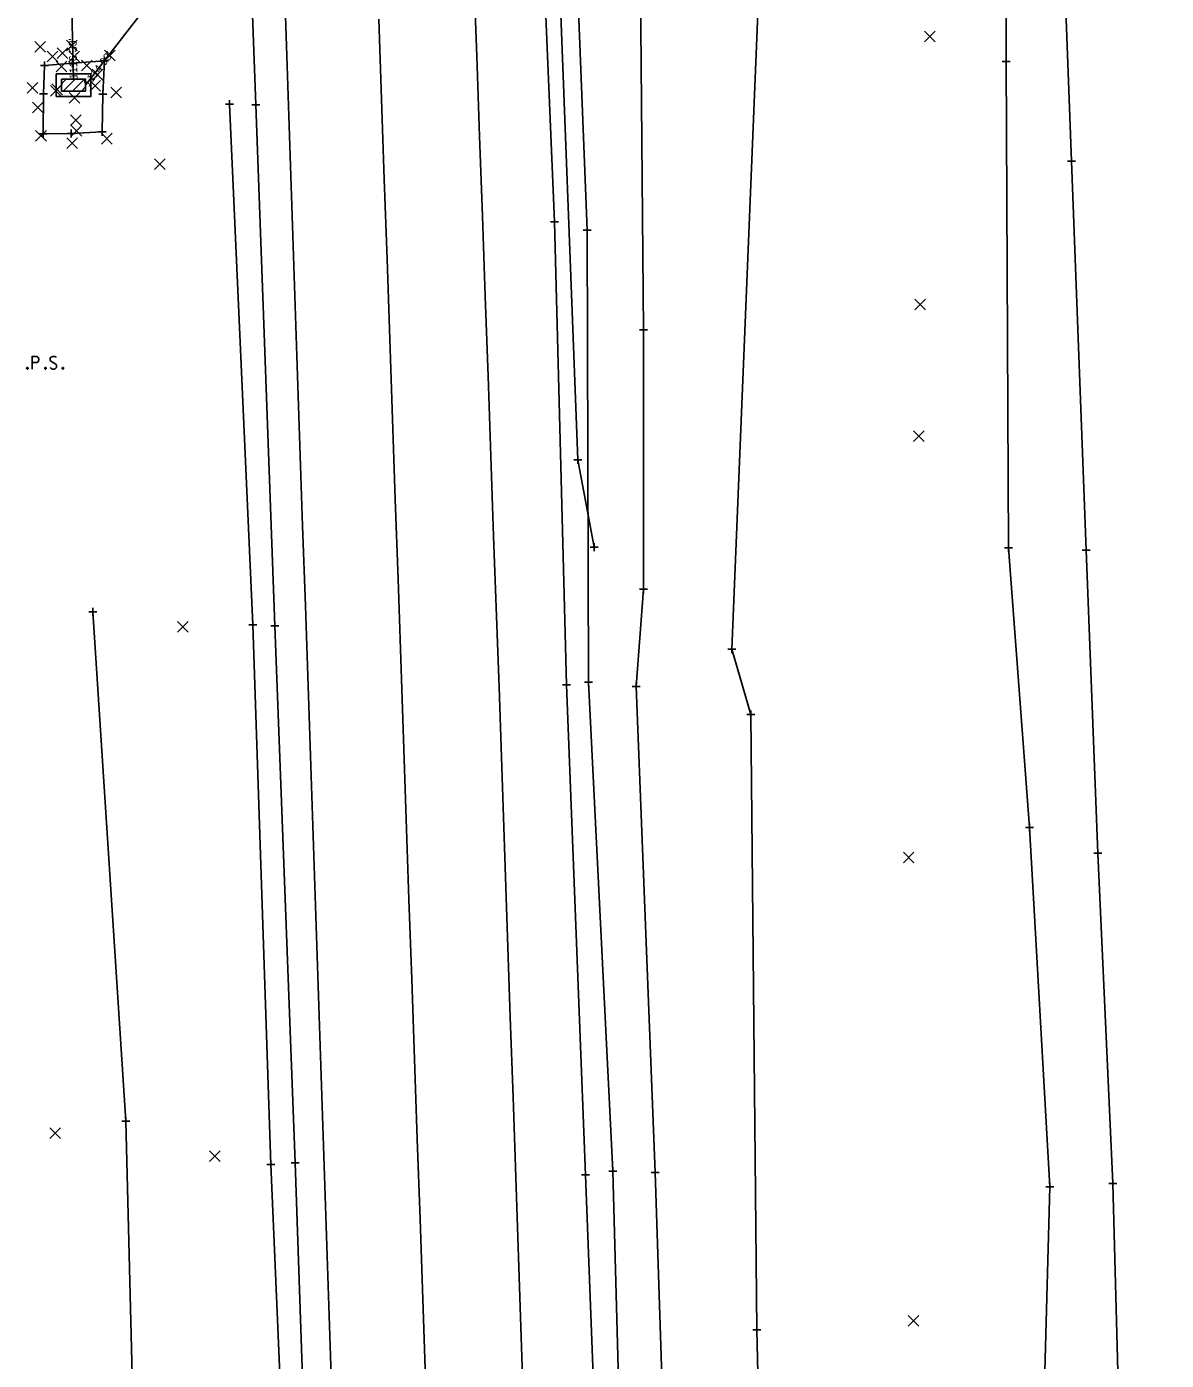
# Model space of a CAD drawing. Extents: x 146022 to 147632, y 437624 to 440659.
# Drawn here: x 146985.9 to 147128.3, y 438299.4 to 438466 of the extents above; entities that cross this region are included whole.
import ezdxf

# ---------------------------------------------------------------- set-up
doc = ezdxf.new("R2010")
doc.units = 0
for name, color, linetype in [('_CIVIL_CONSTRUCTION', 7, 'Continuous'), ('BR_P_Rail_Object', 7, 'Continuous'), ('DR_P_Ditch', 7, 'Continuous'), ('DR_P_Paved_Gutter', 7, 'Continuous'), ('DR_X_Storm_Sewer', 7, 'Continuous'), ('DT_X_Triangles', 7, 'Continuous'), ('PF_X_Ground_Line', 7, 'Continuous'), ('PV_P_Curb', 7, 'Continuous'), ('PV_P_Shoulder', 7, 'Continuous'), ('RD_P_Anchor_Assembly', 7, 'Continuous'), ('RD_P_Fence', 7, 'Continuous'), ('RD_P_GR_Lt_Replaced', 7, 'Continuous'), ('SC_Scratch1', 7, 'Continuous'), ('SC_Scratch3', 7, 'Continuous'), ('SV_X_Terrain_Boundary', 7, 'Continuous'), ('UT_X_Electric', 7, 'Continuous')]:
    doc.layers.add(name, color=color, linetype=linetype)

msp = doc.modelspace()

# ---------------------------------------------------------------- linework, layer by layer
at = {"layer": '_CIVIL_CONSTRUCTION'}
for p, q in [((147098.11, 438464.09), (147099.45, 438465.43)), ((147098.11, 438465.43), (147099.45, 438464.09)), ((146986.96, 438462.83), (146988.3, 438464.16)), ((146986.96, 438464.16), (146988.3, 438462.83)), ((146988.51, 438461.61), (146989.84, 438462.95)), ((146988.51, 438462.95), (146989.84, 438461.61)), ((146989.73, 438462.03), (146991.06, 438463.37)), ((146989.73, 438463.37), (146991.06, 438462.03)), ((146990.9, 438462.99), (146992.23, 438464.32)), ((146990.9, 438464.32), (146992.23, 438462.99)), ((146991.22, 438461.6), (146992.55, 438462.93)), ((146991.22, 438462.93), (146992.55, 438461.6)), ((146995.67, 438461.73), (146997, 438463.06)), ((146995.67, 438463.06), (146997, 438461.73)), ((146989.62, 438460.35), (146990.95, 438461.68)), ((146989.62, 438461.68), (146990.95, 438460.35)), ((146992.77, 438460.48), (146994.1, 438461.82)), ((146992.77, 438461.82), (146994.1, 438460.48)), ((146994.12, 438459.33), (146995.45, 438460.67)), ((146994.12, 438460.67), (146995.45, 438459.33)), ((146985.98, 438457.67), (146987.32, 438459)), ((146985.98, 438459), (146987.32, 438457.67)), ((146988.9, 438457.32), (146990.23, 438458.66)), ((146988.9, 438458.66), (146990.23, 438457.32)), ((146989.09, 438457.5), (146990.42, 438458.84)), ((146989.09, 438458.84), (146990.42, 438457.5)), ((146991.26, 438456.44), (146992.59, 438457.77)), ((146991.26, 438457.77), (146992.59, 438456.44)), ((146993.81, 438457.93), (146995.14, 438459.26)), ((146993.81, 438459.26), (146995.14, 438457.93)), ((146996.44, 438457.11), (146997.78, 438458.44)), ((146996.44, 438458.44), (146997.78, 438457.11)), ((146986.68, 438455.23), (146988.01, 438456.56)), ((146986.68, 438456.56), (146988.01, 438455.23)), ((146991.4, 438453.66), (146992.73, 438454.99)), ((146991.4, 438454.99), (146992.73, 438453.66)), ((146987.05, 438451.69), (146988.39, 438453.03)), ((146987.05, 438453.03), (146988.39, 438451.69)), ((146991.49, 438452.32), (146992.83, 438453.65)), ((146991.49, 438453.65), (146992.83, 438452.32)), ((146990.96, 438450.77), (146992.3, 438452.11)), ((146990.96, 438452.11), (146992.3, 438450.77)), ((146995.28, 438451.33), (146996.61, 438452.67)), ((146995.28, 438452.67), (146996.61, 438451.33)), ((147001.91, 438448.14), (147003.24, 438449.47)), ((147001.91, 438449.47), (147003.24, 438448.14)), ((147096.9, 438430.62), (147098.23, 438431.95)), ((147096.9, 438431.95), (147098.23, 438430.62)), ((147096.74, 438414.17), (147098.07, 438415.51)), ((147096.74, 438415.51), (147098.07, 438414.17)), ((147004.79, 438390.35), (147006.12, 438391.68)), ((147004.79, 438391.68), (147006.12, 438390.35)), ((147095.47, 438361.51), (147096.8, 438362.84)), ((147095.47, 438362.84), (147096.8, 438361.51)), ((146988.83, 438327.07), (146990.16, 438328.41)), ((146988.83, 438328.41), (146990.16, 438327.07)), ((147008.79, 438324.21), (147010.12, 438325.54)), ((147008.79, 438325.54), (147010.12, 438324.21)), ((147096.07, 438303.63), (147097.41, 438304.97)), ((147096.07, 438304.97), (147097.41, 438303.63))]:
    msp.add_line(p, q, dxfattribs=at)
at = {"layer": 'BR_P_Rail_Object'}
for points in [[(147119.79, 438362.73), (147118.32, 438400.57), (147116.48, 438449.21), (147113.81, 438520.22)], [(147128.33, 438146.75), (147127.41, 438176.4), (147123.32, 438258.89), (147121.66, 438321.45), (147119.79, 438362.73)]]:
    msp.add_lwpolyline(points, dxfattribs=at)
at = {"layer": 'DR_P_Ditch'}
msp.add_lwpolyline([(146988, 438452.59), (146988.04, 438457.62), (146988.17, 438461.16), (146991.65, 438461.43), (146995.67, 438461.74), (146995.45, 438457.58), (146995.38, 438452.85), (146991.51, 438452.66)], close=True, dxfattribs=at)
at = {"layer": 'DR_P_Paved_Gutter'}
msp.add_lwpolyline([(147056.84, 438400.98), (147054.81, 438411.86), (147052.17, 438480.63), (147047.3, 438600.68)], dxfattribs=at)
at = {"layer": 'DR_X_Storm_Sewer'}
for p, q in [((146991.79, 438459.44), (146989.6, 438545.12)), ((146993.29, 438458.69), (147010.8, 438481.43))]:
    msp.add_line(p, q, dxfattribs=at)
at = {"layer": 'DT_X_Triangles'}
for p, q in [((146991.79, 438460.11), (146991.79, 438460.11)), ((146991.79, 438459.44), (146991.79, 438459.44)), ((146991.79, 438459.44), (146991.79, 438459.44)), ((146991.79, 438459.44), (146991.79, 438459.44)), ((146990.29, 438458.69), (146990.29, 438458.69)), ((146991.79, 438458.69), (146991.79, 438458.69)), ((146991.79, 438457.94), (146991.79, 438457.94)), ((146993.29, 438458.69), (146993.29, 438458.69)), ((146991.79, 438457.28), (146991.79, 438457.28))]:
    msp.add_line(p, q, dxfattribs=at)
at = {"layer": 'PF_X_Ground_Line'}
for p, q in [((147074.02, 438388.21), (147077.83, 438481.37)), ((147108.63, 438400.88), (147111.24, 438365.93)), ((147074.02, 438388.21), (147076.41, 438380.04))]:
    msp.add_line(p, q, dxfattribs=at)
for points in [[(147108.63, 438400.88), (147108.31, 438461.63), (147108.54, 438516.2)], [(147064.97, 438144.61), (147062.9, 438206.3), (147060.74, 438264.49), (147059.17, 438322.98), (147056.14, 438384.08), (147055.96, 438440.58), (147053.73, 438497.65)], [(147022.87, 438144.98), (147021.12, 438202.84), (147018.92, 438265.58), (147016.42, 438323.84), (147014.17, 438391.24), (147011.28, 438456.3)], [(147076.41, 438380.04), (147077.15, 438303.18), (147078.67, 438238.93), (147079.52, 438175.99), (147079.42, 438144.26)], [(147118.6, 438141.07), (147114.52, 438172.8), (147112.25, 438264.18), (147113.76, 438321.03), (147111.24, 438365.93)]]:
    msp.add_lwpolyline(points, dxfattribs=at)
at = {"layer": 'PV_P_Curb'}
msp.add_lwpolyline([(147035.76, 438297.02), (147035.42, 438307.01), (147035.08, 438317.01), (147034.73, 438327), (147034.39, 438337), (147034.05, 438346.99), (147033.7, 438356.98), (147033.36, 438366.98), (147033.02, 438376.97), (147032.67, 438386.97), (147032.33, 438396.96), (147031.99, 438406.95), (147031.64, 438416.95), (147031.3, 438426.94), (147030.96, 438436.94), (147030.61, 438446.93), (147030.27, 438456.93), (147029.93, 438466.92)], dxfattribs=at)
at = {"layer": 'PV_P_Shoulder'}
for points in [[(146986.6, 438423.2), (146986.6, 438424.8), (146987.13, 438424.8), (146987.19, 438424.79), (146987.27, 438424.76), (146987.3, 438424.74), (146987.33, 438424.71), (146987.38, 438424.65), (146987.41, 438424.59), (146987.43, 438424.49), (146987.43, 438424.34), (146987.42, 438424.29), (146987.4, 438424.21), (146987.35, 438424.12), (146987.31, 438424.08), (146987.28, 438424.06), (146987.22, 438424.03), (146987.13, 438424.02), (146986.6, 438424.02)], [(146989.61, 438424.69), (146989.59, 438424.71), (146989.56, 438424.74), (146989.46, 438424.78), (146989.34, 438424.8), (146989.25, 438424.8), (146989.22, 438424.8), (146989.07, 438424.76), (146988.95, 438424.69), (146988.87, 438424.59), (146988.85, 438424.49), (146988.85, 438424.41), (146988.87, 438424.31), (146988.96, 438424.22), (146989.57, 438423.84), (146989.62, 438423.79), (146989.65, 438423.74), (146989.67, 438423.67), (146989.67, 438423.59), (146989.66, 438423.52), (146989.65, 438423.47), (146989.62, 438423.4), (146989.6, 438423.35), (146989.58, 438423.32), (146989.55, 438423.28), (146989.51, 438423.25), (146989.47, 438423.23), (146989.44, 438423.21), (146989.34, 438423.2), (146989.18, 438423.2), (146989.08, 438423.23), (146988.94, 438423.32), (146988.85, 438423.39)], [(146986, 438423.42), (146986.05, 438423.42), (146986.09, 438423.39), (146986.12, 438423.34), (146986.12, 438423.28), (146986.09, 438423.23), (146986.05, 438423.2), (146986, 438423.2), (146985.96, 438423.23), (146985.93, 438423.28), (146985.93, 438423.34), (146985.96, 438423.39), (146986, 438423.42)], [(146988.25, 438423.42), (146988.3, 438423.42), (146988.33, 438423.39), (146988.37, 438423.34), (146988.37, 438423.28), (146988.33, 438423.23), (146988.3, 438423.2), (146988.25, 438423.2), (146988.21, 438423.23), (146988.18, 438423.28), (146988.18, 438423.34), (146988.21, 438423.39), (146988.25, 438423.42)], [(146990.43, 438423.42), (146990.48, 438423.42), (146990.52, 438423.39), (146990.55, 438423.34), (146990.55, 438423.28), (146990.52, 438423.23), (146990.48, 438423.2), (146990.43, 438423.2), (146990.4, 438423.23), (146990.36, 438423.28), (146990.36, 438423.34), (146990.4, 438423.39), (146990.43, 438423.42)]]:
    msp.add_lwpolyline(points, dxfattribs=at)
at = {"layer": 'RD_P_Anchor_Assembly'}
for p, q in [((146987.67, 438461.16), (146988.67, 438461.16)), ((146988.17, 438461.66), (146988.17, 438460.66)), ((146988.17, 438461.16), (146988.17, 438461.16)), ((146991.15, 438461.43), (146992.15, 438461.43)), ((146991.65, 438461.93), (146991.65, 438460.93)), ((146991.65, 438461.43), (146991.65, 438461.43)), ((146995.17, 438461.74), (146996.17, 438461.74)), ((146995.67, 438462.24), (146995.67, 438461.24)), ((146995.67, 438461.74), (146995.67, 438461.74)), ((147107.81, 438461.63), (147108.81, 438461.63)), ((147108.31, 438462.13), (147108.31, 438461.13)), ((147108.31, 438461.63), (147108.31, 438461.63)), ((146988.04, 438458.12), (146988.04, 438457.12)), ((146995.45, 438458.08), (146995.45, 438457.08)), ((146987.54, 438457.62), (146988.54, 438457.62)), ((146988.04, 438457.62), (146988.04, 438457.62)), ((146994.95, 438457.58), (146995.95, 438457.58)), ((146995.45, 438457.58), (146995.45, 438457.58)), ((147010.78, 438456.3), (147011.78, 438456.3)), ((147011.28, 438456.8), (147011.28, 438455.8)), ((147011.28, 438456.3), (147011.28, 438456.3)), ((147014.05, 438456.21), (147015.05, 438456.21)), ((147014.55, 438456.71), (147014.55, 438455.71)), ((147014.55, 438456.21), (147014.55, 438456.21)), ((146988, 438453.09), (146988, 438452.09)), ((146991.51, 438453.16), (146991.51, 438452.16)), ((146994.88, 438452.85), (146995.88, 438452.85)), ((146995.38, 438453.35), (146995.38, 438452.35)), ((146995.38, 438452.85), (146995.38, 438452.85)), ((146987.5, 438452.59), (146988.5, 438452.59)), ((146988, 438452.59), (146988, 438452.59)), ((146991.01, 438452.66), (146992.01, 438452.66)), ((146991.51, 438452.66), (146991.51, 438452.66)), ((147116.48, 438449.71), (147116.48, 438448.71)), ((147115.98, 438449.21), (147116.98, 438449.21)), ((147116.48, 438449.21), (147116.48, 438449.21)), ((147051.4, 438441.59), (147052.4, 438441.59)), ((147051.9, 438442.09), (147051.9, 438441.09)), ((147051.9, 438441.59), (147051.9, 438441.59)), ((147055.96, 438441.08), (147055.96, 438440.08)), ((147055.46, 438440.58), (147056.46, 438440.58)), ((147055.96, 438440.58), (147055.96, 438440.58)), ((147062.49, 438428.1), (147063.49, 438428.1)), ((147062.99, 438428.6), (147062.99, 438427.6)), ((147062.99, 438428.1), (147062.99, 438428.1)), ((147054.31, 438411.86), (147055.31, 438411.86)), ((147054.81, 438412.36), (147054.81, 438411.36)), ((147054.81, 438411.86), (147054.81, 438411.86)), ((147056.84, 438401.48), (147056.84, 438400.48)), ((147108.63, 438401.38), (147108.63, 438400.38)), ((147056.34, 438400.98), (147057.34, 438400.98)), ((147056.84, 438400.98), (147056.84, 438400.98)), ((147108.13, 438400.88), (147109.13, 438400.88)), ((147108.63, 438400.88), (147108.63, 438400.88)), ((147117.82, 438400.57), (147118.82, 438400.57)), ((147118.32, 438401.07), (147118.32, 438400.07)), ((147118.32, 438400.57), (147118.32, 438400.57)), ((147063.01, 438396.22), (147063.01, 438395.22)), ((147062.51, 438395.72), (147063.51, 438395.72)), ((147063.01, 438395.72), (147063.01, 438395.72)), ((146993.7, 438392.86), (146994.7, 438392.86)), ((146994.2, 438393.36), (146994.2, 438392.36)), ((146994.2, 438392.86), (146994.2, 438392.86)), ((147013.67, 438391.24), (147014.67, 438391.24)), ((147014.17, 438391.74), (147014.17, 438390.74)), ((147014.17, 438391.24), (147014.17, 438391.24)), ((147016.44, 438391.13), (147017.44, 438391.13)), ((147016.94, 438391.63), (147016.94, 438390.63)), ((147016.94, 438391.13), (147016.94, 438391.13)), ((147073.52, 438388.21), (147074.52, 438388.21)), ((147074.02, 438388.71), (147074.02, 438387.71)), ((147074.02, 438388.21), (147074.02, 438388.21)), ((147056.14, 438384.58), (147056.14, 438383.58)), ((147052.89, 438383.76), (147053.89, 438383.76)), ((147053.39, 438384.26), (147053.39, 438383.26)), ((147053.39, 438383.76), (147053.39, 438383.76)), ((147055.64, 438384.08), (147056.64, 438384.08)), ((147056.14, 438384.08), (147056.14, 438384.08)), ((147061.57, 438383.55), (147062.57, 438383.55)), ((147062.07, 438384.05), (147062.07, 438383.05)), ((147062.07, 438383.55), (147062.07, 438383.55)), ((147075.91, 438380.04), (147076.91, 438380.04)), ((147076.41, 438380.54), (147076.41, 438379.54)), ((147076.41, 438380.04), (147076.41, 438380.04)), ((147111.24, 438366.43), (147111.24, 438365.43)), ((147110.74, 438365.93), (147111.74, 438365.93)), ((147111.24, 438365.93), (147111.24, 438365.93)), ((147119.79, 438363.23), (147119.79, 438362.23)), ((147119.29, 438362.73), (147120.29, 438362.73)), ((147119.79, 438362.73), (147119.79, 438362.73)), ((146998.32, 438329.74), (146998.32, 438328.74)), ((146997.82, 438329.24), (146998.82, 438329.24)), ((146998.32, 438329.24), (146998.32, 438329.24)), ((147019.46, 438324.52), (147019.46, 438323.52)), ((147015.92, 438323.84), (147016.92, 438323.84)), ((147016.42, 438324.34), (147016.42, 438323.34)), ((147016.42, 438323.84), (147016.42, 438323.84)), ((147018.96, 438324.02), (147019.96, 438324.02)), ((147019.46, 438324.02), (147019.46, 438324.02)), ((147055.74, 438323.04), (147055.74, 438322.04)), ((147058.67, 438322.98), (147059.67, 438322.98)), ((147059.17, 438323.48), (147059.17, 438322.48)), ((147059.17, 438322.98), (147059.17, 438322.98)), ((147063.97, 438322.84), (147064.97, 438322.84)), ((147064.47, 438323.34), (147064.47, 438322.34)), ((147064.47, 438322.84), (147064.47, 438322.84)), ((147055.24, 438322.54), (147056.24, 438322.54)), ((147055.74, 438322.54), (147055.74, 438322.54)), ((147113.76, 438321.53), (147113.76, 438320.53)), ((147121.16, 438321.45), (147122.16, 438321.45)), ((147121.66, 438321.95), (147121.66, 438320.95)), ((147121.66, 438321.45), (147121.66, 438321.45)), ((147113.26, 438321.03), (147114.26, 438321.03)), ((147113.76, 438321.03), (147113.76, 438321.03)), ((147076.65, 438303.18), (147077.65, 438303.18)), ((147077.15, 438303.68), (147077.15, 438302.68)), ((147077.15, 438303.18), (147077.15, 438303.18))]:
    msp.add_line(p, q, dxfattribs=at)
at = {"layer": 'RD_P_Fence'}
for points in [[(147065.6, 438549.68), (147065.06, 438542.78), (147063.25, 438518.16), (147062.43, 438494.35), (147062.99, 438428.1), (147063.01, 438395.72)], [(147070.61, 438144.09), (147068.37, 438204.92), (147068.38, 438204.92), (147066.32, 438265.45), (147064.47, 438322.84), (147062.07, 438383.55), (147063.01, 438395.72)], [(146994.2, 438392.86), (146998.32, 438329.24), (146999.72, 438272.48), (147000.9, 438206.1), (147002.95, 438145.15)]]:
    msp.add_lwpolyline(points, dxfattribs=at)
at = {"layer": 'RD_P_GR_Lt_Replaced'}
msp.add_line((147011.85, 438534.06), (147014.55, 438456.21), dxfattribs=at)
for points in [[(147062.34, 438143.95), (147060.09, 438206), (147058.01, 438263.66), (147055.74, 438322.54), (147053.39, 438383.76), (147051.9, 438441.59), (147049.52, 438498.04)], [(147025.86, 438145.05), (147023.62, 438202.72), (147021.48, 438265.46), (147019.46, 438324.02), (147016.94, 438391.13), (147014.55, 438456.21)]]:
    msp.add_lwpolyline(points, dxfattribs=at)
at = {"layer": 'SC_Scratch3'}
for points in [[(147024.11, 438293.68), (147023.78, 438303.68), (147023.44, 438313.67), (147023.1, 438323.67), (147022.77, 438333.66), (147022.43, 438343.66), (147022.09, 438353.65), (147021.76, 438363.64), (147021.42, 438373.64), (147021.09, 438383.63), (147020.75, 438393.63), (147020.41, 438403.62), (147020.08, 438413.62), (147019.74, 438423.61), (147019.4, 438433.6), (147019.07, 438443.6), (147018.73, 438453.59), (147018.39, 438463.59), (147018.06, 438473.58)], [(147041.82, 438472.29), (147042.18, 438462.3), (147042.53, 438452.3), (147042.88, 438442.31), (147043.23, 438432.32), (147043.58, 438422.32), (147043.93, 438412.33), (147044.28, 438402.34), (147044.64, 438392.34), (147044.99, 438382.35), (147044.99, 438382.22), (147045.33, 438372.23), (147045.67, 438362.24), (147046.02, 438352.24), (147046.36, 438342.25), (147046.7, 438332.25), (147047.04, 438322.26), (147047.38, 438312.26), (147047.73, 438302.27), (147048.07, 438292.28)]]:
    msp.add_lwpolyline(points, dxfattribs=at)
at = {"layer": 'SV_X_Terrain_Boundary'}
msp.add_lwpolyline([(147123.32, 438258.89), (147121.66, 438321.45), (147119.79, 438362.73), (147118.32, 438400.57), (147116.48, 438449.21), (147113.81, 438520.22)], dxfattribs=at)
at = {"layer": 'UT_X_Electric'}
for p, q in [((146990.29, 438459.44), (146990.8, 438459.44)), ((146990.29, 438458.88), (146990.29, 438459.44)), ((146990.29, 438458.86), (146990.87, 438459.44)), ((146990.51, 438457.94), (146992.01, 438459.44)), ((146991.18, 438459.44), (146991.6, 438459.44)), ((146991.64, 438457.94), (146993.14, 438459.44)), ((146992.01, 438459.44), (146992.4, 438459.44)), ((146992.78, 438459.44), (146993.29, 438459.44)), ((146993.29, 438459.44), (146993.29, 438458.88)), ((146990.29, 438457.94), (146990.29, 438458.51)), ((146990.8, 438457.94), (146990.29, 438457.94)), ((146991.6, 438457.94), (146991.18, 438457.94)), ((146992.4, 438457.94), (146991.98, 438457.94)), ((146992.77, 438457.94), (146993.29, 438458.46)), ((146993.29, 438457.94), (146992.78, 438457.94)), ((146993.29, 438458.51), (146993.29, 438457.94))]:
    msp.add_line(p, q, dxfattribs=at)
for points in [[(146989.62, 438460.11), (146993.96, 438460.11), (146993.96, 438457.28), (146989.62, 438457.28)], [(146990.29, 438459.44), (146993.29, 438459.44), (146993.29, 438457.94), (146990.29, 438457.94)], [(146990.29, 438459.44), (146993.29, 438459.44), (146993.29, 438457.94), (146990.29, 438457.94)]]:
    msp.add_lwpolyline(points, close=True, dxfattribs=at)

# ---------------------------------------------------------------- texts
at = {"layer": 'SC_Scratch1'}
for s, rotation, p in [("1116.33'", 91.4646, (146992.29, 438459.46)), ("1114.93'", 52.4049, (146993.68, 438458.39))]:
    msp.add_text(s, height=1, rotation=rotation, dxfattribs=at).set_placement(p)

doc.saveas('drawing.dxf')
